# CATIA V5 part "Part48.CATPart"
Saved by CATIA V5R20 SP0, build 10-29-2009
Part number: FA 042200-1
Revision: ANY
Definition: UNKNOWN
Nomenclature: FA 042200-1
Source: Unknown
Bounding box of the stored display mesh (mm): x 0.374 to 3.8, y -1.58 to 1.58, z -1.58 to 1.58
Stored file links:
  C:\Users\Utente\Desktop\IO LAVORO\3D X SITO CF\CUMSA\3D files FA\FA 042204-20\Part48.CATPart

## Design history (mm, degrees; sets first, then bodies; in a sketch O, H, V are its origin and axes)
Body1 "Cortar-Extruir2" (main body)
  Solid1: solid without history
